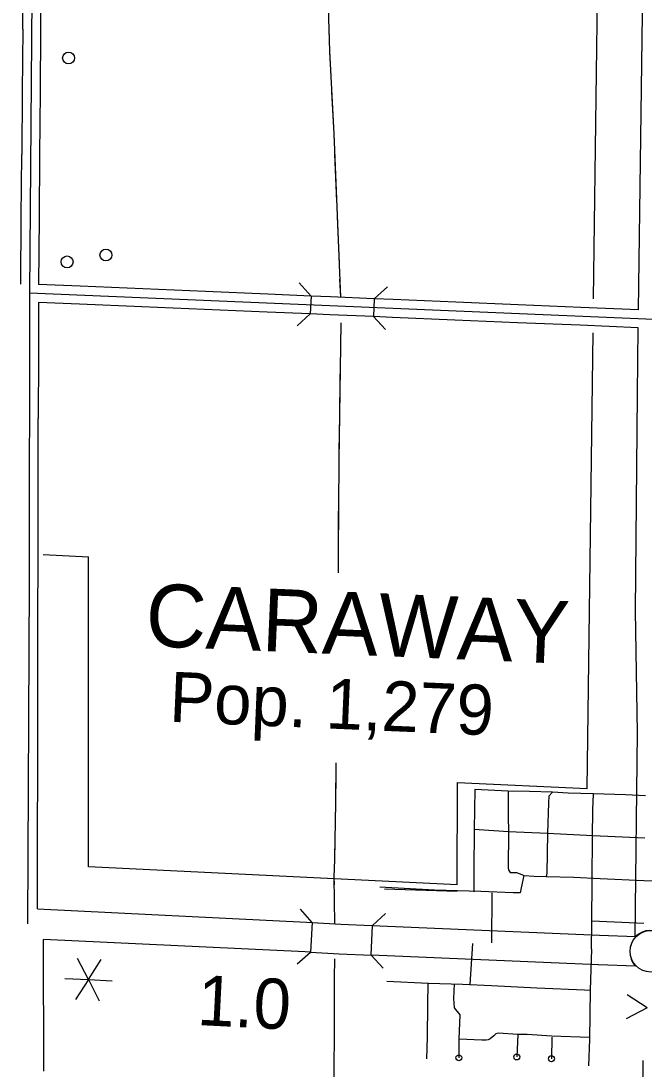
# Model space of a CAD drawing. Extents: x -4306 to 3843, y 131 to 8053.
# Drawn here: x -251 to 589, y 3441 to 4853 of the extents above; entities that cross this region are included whole.
import ezdxf

# ---------------------------------------------------------------- set-up
doc = ezdxf.new("R2010")
doc.units = 0
for name, color, linetype in [('10', 7, 'Continuous'), ('24', 7, 'Continuous'), ('31', 7, 'Continuous'), ('32', 7, 'Continuous'), ('33', 7, 'Continuous'), ('37', 7, 'Continuous'), ('38', 7, 'Continuous'), ('43', 7, 'Continuous'), ('48', 7, 'Continuous'), ('56', 7, 'Continuous'), ('6', 7, 'Continuous')]:
    doc.layers.add(name, color=color, linetype=linetype)

msp = doc.modelspace()

# ---------------------------------------------------------------- linework, layer by layer
at = {"layer": '10'}
for p, q in [((141.8, 3638.2), (139.4, 3598.3)), ((141.9, 3638.2), (180.4, 3636)), ((180.4, 3636), (222.3, 3634.2)), ((221.4, 3594.2), (223.1, 3634.1)), ((-220.3, 3437.9), (-220.6, 3615.3)), ((139.3, 3598.3), (178.3, 3596)), ((178.3, 3596), (221.6, 3594.2))]:
    msp.add_line(p, q, dxfattribs=at)
for points in [[(581.8, 4463.7), (592.6, 5261.1), (598.4, 5277.4), (608.7, 5295.2), (624.9, 5312.8), (658.1, 5334.6), (688.3, 5342.8), (970.2, 5330.2)], [(577.7, 4058.2), (580.3, 4349.6), (581.5, 4439.7)], [(577.5, 3619.1), (580.3, 3893.9), (577.7, 4058.2)], [(-228.8, 3656.8), (134.2, 3638.7), (141.9, 3638.2)], [(222.3, 3634.2), (529.3, 3621)], [(529.1, 3621), (578, 3619.5)], [(139.3, 3598.3), (132.1, 3598.7), (-220.6, 3615.3)], [(527.6, 3581.1), (221.6, 3594.2)], [(577.7, 3579.5), (527.8, 3581.1)]]:
    msp.add_lwpolyline(points, dxfattribs=at)
for centre, radius, start, end in [((599.7, 3599.3), 29.6, 137.0643, 221.959), ((598.1, 3598.2), 29.3, 48.5826, 134.7506)]:
    msp.add_arc(centre, radius, start, end, dxfattribs=at)
at = {"layer": '24'}
msp.add_circle((598.4, 3599.4), 28, dxfattribs=at)
at = {"layer": '31'}
for p, q in [((-248.6, 4842.2), (-249.2, 4757.7)), ((-224.6, 4842), (-225.2, 4757.5)), ((-249.2, 4757.7), (-249.9, 4673.2)), ((-225.2, 4757.5), (-225.9, 4673)), ((-227.3, 4474), (-227.4, 4402)), ((-227.4, 4402), (-227.6, 4317.5)), ((-240, 4096.4), (-242, 3636.2)), ((239.5, 3683.8), (337.1, 3680.5))]:
    msp.add_line(p, q, dxfattribs=at)
for points in [[(-248.6, 4842.2), (-248, 4926.7)], [(-224, 4926.5), (-224.6, 4842)], [(-250.5, 4588.7), (-249.9, 4673.2)], [(-225.9, 4673), (-226.5, 4588.5)], [(-251.2, 4498.7), (-250.5, 4588.7)], [(-226.5, 4588.5), (-227.2, 4498)], [(-227.7, 4233), (-227.6, 4317.5)], [(-228.8, 3656.8), (-227.7, 4233)]]:
    msp.add_lwpolyline(points, dxfattribs=at)
at = {"layer": '32'}
for p, q in [((-232.8, 5349), (-239.3, 4486.5)), ((-171.2, 4495.7), (-227.2, 4498)), ((-86.7, 4492.1), (-171.2, 4495.7)), ((-2.3, 4488.5), (-86.7, 4492.1)), ((-239.3, 4486.5), (-240, 4096.4)), ((602.5, 4450.9), (-239.3, 4486.5)), ((82.1, 4484.9), (-2.3, 4488.5)), ((140.2, 4482.5), (82.1, 4484.9)), ((140.2, 4482.5), (139.1, 4458.5)), ((166.5, 4481.3), (140.2, 4482.5)), ((225.5, 4478.8), (166.5, 4481.3)), ((225.5, 4478.8), (224.5, 4454.9)), ((250.9, 4477.8), (225.5, 4478.8)), ((335.3, 4474.2), (250.9, 4477.8)), ((-172.2, 4471.7), (-227.3, 4474)), ((-87.8, 4468.1), (-172.2, 4471.7)), ((-3.3, 4464.5), (-87.8, 4468.1)), ((81.1, 4460.9), (-3.3, 4464.5)), ((419.7, 4470.6), (335.3, 4474.2)), ((504.2, 4467), (419.7, 4470.6)), ((581.8, 4463.7), (504.2, 4467)), ((139.1, 4458.5), (81.1, 4460.9)), ((165.5, 4457.4), (139.1, 4458.5)), ((224.5, 4454.9), (165.5, 4457.4)), ((249.9, 4453.8), (224.5, 4454.9)), ((334.3, 4450.2), (249.9, 4453.8)), ((418.7, 4446.6), (334.3, 4450.2)), ((503.1, 4443.1), (418.7, 4446.6)), ((581.5, 4439.7), (503.1, 4443.1))]:
    msp.add_line(p, q, dxfattribs=at)
at = {"layer": '33'}
for p, q in [((361, 3817.6), (360.1, 3763.4)), ((406.1, 3815.4), (361, 3817.6)), ((434.6, 3814.6), (406.1, 3815.4)), ((406.1, 3815.4), (406.2, 3781.4)), ((466, 3813.7), (434.6, 3814.6)), ((461, 3808.4), (460.3, 3799.6)), ((466, 3813.7), (461, 3808.4)), ((486.8, 3812.7), (466, 3813.7)), ((521.1, 3811.6), (486.8, 3812.7)), ((520.3, 3790.7), (521.2, 3811.3)), ((564.4, 3810.1), (521.1, 3811.6)), ((591.3, 3809), (564.4, 3810.1)), ((460.3, 3799.6), (459.1, 3758.2)), ((519.9, 3753), (520.3, 3790.7)), ((406.2, 3781.4), (406.4, 3760.2)), ((360.1, 3763.4), (359.8, 3708.5)), ((406.4, 3760.5), (360.1, 3763.4)), ((406.4, 3760.2), (406, 3711.5)), ((459.1, 3758.2), (406.4, 3760.5)), ((459.1, 3758.2), (458, 3704.8)), ((520, 3754.9), (459.1, 3758.2)), ((519.4, 3696.5), (519.9, 3753)), ((590.2, 3751.8), (520, 3754.9)), ((359.8, 3708.5), (359.6, 3679.4)), ((406, 3711.5), (407.1, 3708.5)), ((407.1, 3708.5), (408.7, 3705.8)), ((408.7, 3705.8), (411, 3705.4)), ((411, 3705.4), (417.2, 3705.4)), ((417.2, 3705.4), (424.4, 3702.9)), ((427.3, 3701.6), (423.5, 3685.1)), ((424.4, 3702.9), (427.3, 3701.6)), ((427.3, 3701.6), (441, 3700.7)), ((458, 3704.8), (457.2, 3700.2)), ((441, 3700.7), (457.2, 3700.2)), ((457.2, 3700.2), (494.4, 3699.2)), ((494.4, 3699.2), (529.9, 3697.5)), ((518.8, 3636.8), (519.4, 3696.5)), ((529.9, 3697.5), (589, 3694.9)), ((589, 3694.9), (639.6, 3693.2)), ((306.8, 3682), (233, 3685.9)), ((369, 3679.8), (306.8, 3682)), ((412.6, 3678.3), (369, 3679.8)), ((383.9, 3610.7), (384.5, 3678.2)), ((422.3, 3678.1), (412.6, 3678.3)), ((423.5, 3685.1), (422.3, 3678.1)), ((518.2, 3602.2), (518.8, 3636.8)), ((519.4, 3640.3), (588.9, 3637.3)), ((358.1, 3610), (354.5, 3554.5)), ((518.2, 3602.2), (516.4, 3547)), ((242.5, 3559.1), (298.6, 3556.6)), ((297.7, 3556.7), (297.1, 3526.9)), ((298.6, 3556.6), (344.3, 3555)), ((333.1, 3555.4), (332.3, 3535.9)), ((344.3, 3555), (383.4, 3553.1)), ((383.4, 3553.1), (444.7, 3550.1)), ((444.7, 3550.1), (509.1, 3547.5)), ((509.1, 3547.5), (516.4, 3547)), ((516.4, 3547), (515.5, 3481.1)), ((332.3, 3535.9), (333, 3523.4)), ((297.1, 3526.9), (296.9, 3484.2)), ((333, 3523.4), (340.8, 3513.7)), ((340.8, 3513.7), (339.4, 3481.1)), ((296.9, 3484.2), (296.1, 3454.3)), ((339.4, 3481.1), (339.5, 3455.9)), ((370.6, 3479.5), (340, 3480.9)), ((376.5, 3479.4), (370.6, 3479.5)), ((379, 3479.9), (376.5, 3479.4)), ((381.7, 3481.5), (379, 3479.9)), ((386.5, 3485.6), (381.7, 3481.5)), ((389.5, 3488), (386.5, 3485.6)), ((392.6, 3488.9), (389.5, 3488)), ((419.2, 3487.4), (392.6, 3488.9)), ((419.2, 3487.4), (417.6, 3457)), ((431.8, 3487.1), (419.2, 3487.4)), ((465, 3485.2), (431.8, 3487.1)), ((464.8, 3483.6), (464.4, 3454.6)), ((515.6, 3483), (465, 3485.2)), ((515.5, 3481.1), (514.4, 3445)), ((587.5, 3452.1), (587.2, 3395.7))]:
    msp.add_line(p, q, dxfattribs=at)
for centre in [(417.6, 3457), (339.5, 3455.9), (464.4, 3454.6)]:
    msp.add_circle(centre, 4, dxfattribs=at)
at = {"layer": '37'}
for p, q in [((140.6, 3618.3), (140.6, 3618.3)), ((222.3, 3614.1), (222.3, 3614.1))]:
    msp.add_line(p, q, dxfattribs=at)
for points in [[(141.8, 3638.2), (125.8, 3656.2)], [(240.8, 3650.4), (223.1, 3634.1)], [(121.5, 3582.4), (139.4, 3598.3)], [(221.4, 3594.2), (237.6, 3576.5)]]:
    msp.add_lwpolyline(points, dxfattribs=at)
at = {"layer": '38'}
for points in [[(124, 4500.1), (140.2, 4482.5)], [(225.5, 4478.8), (243.2, 4495.1)], [(139.2, 4458.5), (121.5, 4442.2)], [(240.7, 4437.2), (224.5, 4454.9)]]:
    msp.add_lwpolyline(points, dxfattribs=at)
at = {"layer": '43'}
for points in [[(145, 5317.6), (147, 5284.2), (150.3, 5227.5), (151.6, 5159.7), (156.3, 5066.2), (161.9, 4915.7), (165.2, 4812.6), (170.9, 4701), (174.9, 4602.5), (179.8, 4480.8)], [(164.3, 4842.7), (165.2, 4812.6), (165.3, 4811.1)], [(165.3, 4811.1), (166.9, 4779.4)], [(168, 4758.3), (170.9, 4701), (171.1, 4695.1)], [(172, 4673.9), (174.6, 4610.6)], [(175.4, 4589.5), (178, 4526.2)], [(178.8, 4505.1), (179.8, 4480.8)], [(180.3, 4446.2), (177.7, 4261), (176.6, 4135.8), (176.6, 4109.4)], [(180.3, 4446.2), (179.8, 4414.5)], [(179.5, 4393.4), (178.6, 4330)], [(178.3, 4308.9), (177.7, 4261), (177.5, 4245.5)], [(177.4, 4224.4), (176.9, 4161)], [(176.7, 4139.9), (176.6, 4135.8), (176.6, 4109.4)], [(172.3, 3636.3), (171.5, 3699.2), (172.2, 3723.3), (173.7, 3799.8), (174.2, 3853.6)], [(173.2, 3773.6), (173.7, 3799.8), (174, 3836.9)], [(171.7, 3689.1), (171.5, 3699.2), (172.2, 3723.3), (172.8, 3752.5)], [(172.3, 3636.3), (171.9, 3668)], [(171.8, 3589.1), (171.4, 3563.3), (171.3, 3496.1), (171, 3432.6), (172.2, 3333.7), (171.4, 3260.5), (172.2, 3153.3), (173.3, 3061.5), (170.6, 2998.5), (169.4, 2887.7), (169.9, 2831.1), (169.7, 2779.7), (168.3, 2589.1), (167.2, 2425), (167.8, 2378)], [(171.8, 3589.1), (171.4, 3563.3), (171.4, 3557.4)], [(171.4, 3536.3), (171.3, 3496.1), (171.2, 3472.9)], [(171.1, 3451.8), (171, 3432.6), (171.5, 3388.4)]]:
    msp.add_lwpolyline(points, dxfattribs=at)
at = {"layer": '48'}
for p, q in [((-160, 3561.3), (-174.6, 3589.7)), ((-160, 3561.3), (-142.7, 3588.2)), ((-192, 3562.8), (-160, 3561.3)), ((-160, 3561.3), (-177.3, 3534.4)), ((-160, 3561.3), (-128, 3559.7)), ((-160, 3561.3), (-145.4, 3532.8)), ((593.6, 3523.3), (566.7, 3540.6)), ((593.6, 3523.3), (565.1, 3508.6))]:
    msp.add_line(p, q, dxfattribs=at)
at = {"layer": '56'}
for centre in [(-186.7, 4803.3), (-188.7, 4528.5), (-136.4, 4537.8)]:
    msp.add_circle(centre, 8, dxfattribs=at)
at = {"layer": '6'}
for p, q in [((521.1, 4478.6), (532, 5325.5)), ((512.6, 3818.7), (520.5, 4433)), ((-221.2, 4134.2), (-159.7, 4131.2))]:
    msp.add_line(p, q, dxfattribs=at)
for points in [[(337.2, 3688.8), (-159.8, 3713.1), (-159.7, 4131.2)], [(337.2, 3688.8), (337.8, 3827), (512.6, 3818.7)]]:
    msp.add_lwpolyline(points, dxfattribs=at)

# ---------------------------------------------------------------- texts
at = {"layer": '48'}
msp.add_text('1.0', height=67.59, rotation=357.1416, dxfattribs=at).set_placement((-14.1, 3500.1))
at = {"layer": '6'}
for s, height, p in [('CARAWAY', 84.49, (-84.1, 4010.9)), ('Pop. 1,279', 67.59, (-51.7, 3908.8))]:
    msp.add_text(s, height=height, rotation=357.5729, dxfattribs=at).set_placement(p)

doc.saveas('drawing.dxf')
